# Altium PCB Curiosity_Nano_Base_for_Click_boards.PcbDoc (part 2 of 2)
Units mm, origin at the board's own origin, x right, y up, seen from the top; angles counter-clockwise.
Board outline 74.93 x 107.95 mm, 4 copper layers (Top Layer, Internal Plane 1 Gnd, Internal Plane 2 Pwr, Bottom Layer), stack 1.565 mm thick; 66 components, 59 nets, 464 pads, 89 vias.
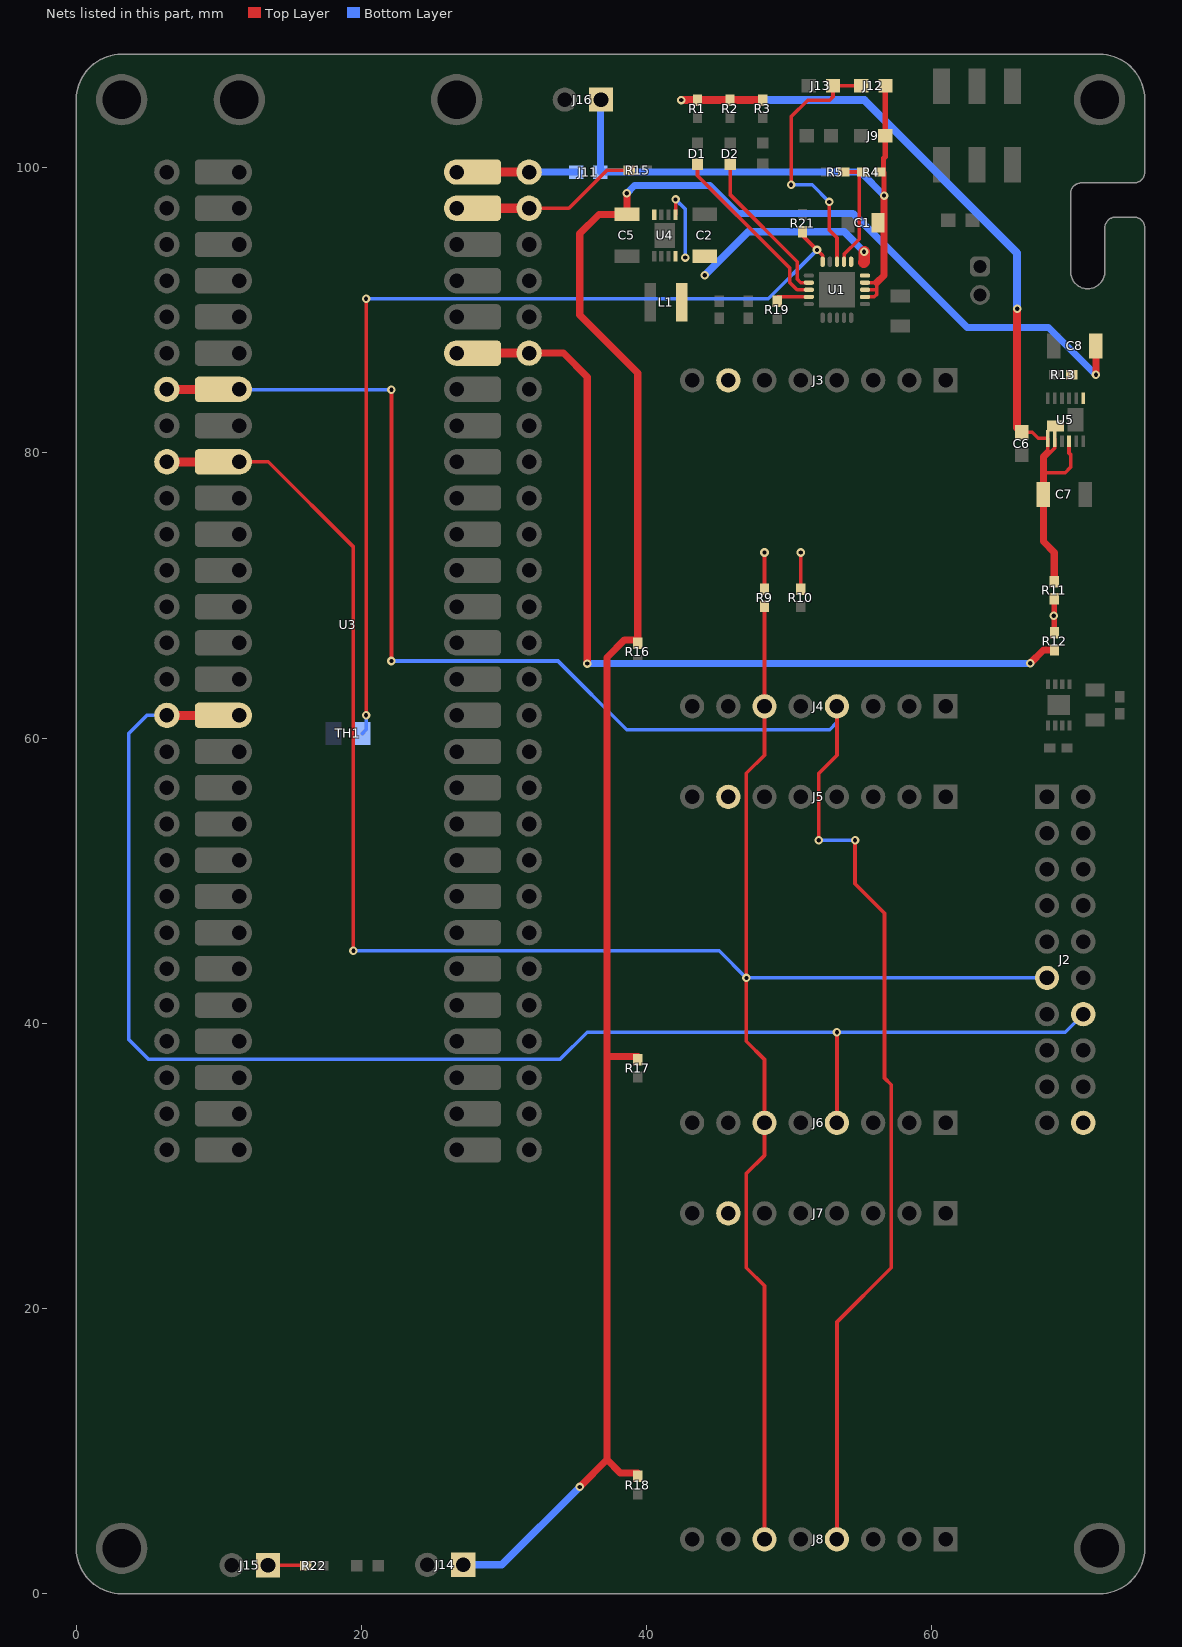
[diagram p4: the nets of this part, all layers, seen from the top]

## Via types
v1: diameter 0.6, hole 0.3, Top Layer to Bottom Layer, tented both sides, 83 vias
v2: diameter 0.6, hole 0.3, Top Layer to Bottom Layer, 6 vias

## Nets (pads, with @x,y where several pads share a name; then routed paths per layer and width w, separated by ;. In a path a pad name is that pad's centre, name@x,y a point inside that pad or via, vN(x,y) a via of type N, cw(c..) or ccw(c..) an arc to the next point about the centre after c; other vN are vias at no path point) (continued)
SDA: J2.11 J4.6 J6.6 J8.6 R9.2 U3.9 | length 155.6
  Top Layer w0.254: U3.9@11.43,79.375 13.462,79.375 19.431,73.406 v1(19.431,45.085) ; R9.2@48.133,69 48.26,68.873 J4.6@48.26,62.23 48.26,58.801 46.99,57.531 v1(46.99,43.18) 46.99,38.735 48.26,37.465 J6.6@48.26,33.02 48.26,30.734 46.99,29.464 46.99,22.86 48.26,21.59 J8.6@48.26,3.81
  Bottom Layer w0.254: v1(19.431,45.085) 42.418,45.085 45.085,45.085 v1(46.99,43.18) J2.11@68.072,43.18
SEL: J12.1 J13.2 U1.3 | length 18.6
  Top Layer w0.254: v2(50.125,98.8) 50.125,103.575 51.29,104.74 52.826,104.74 53.062,104.976 J13.2@53.062,105.75 J12.1@55.05,105.75 ; v2(52.8,97.6) 52.8,95.625 53.34,95.085 U1.3@53.34,93.405
  Bottom Layer w0.254: v2(50.125,98.8) 51.6,98.8 v2(52.8,97.6)
STAT1: D1.1 U1.8 | length 12.5
  Top Layer w0.254: D1.1@43.561,100.23 43.561,99.441 50.038,92.964 50.038,91.948 50.546,91.44 U1.8@51.375,91.44
STAT2: D2.1 U1.7 | length 10.9
  Top Layer w0.254: D2.1@45.847,100.23 45.847,98.122 50.559,93.41 50.559,92.189 50.808,91.94 U1.7@51.375,91.94
T\E\: R19.1 U1.9 | length 2.2
  Top Layer w0.254: R19.1@49.149,90.893 49.196,90.94 U1.9@51.375,90.94
THERM: R21.1 TH1.1 U1.5 | length 66.3
  Top Layer w0.254: v1(20.32,61.595) v1(20.32,90.805) ; R21.1@50.927,95.504 50.927,95.25 v1(51.943,94.234) 52.34,93.837 U1.5@52.34,93.405
  Bottom Layer w0.254: TH1.1@20.066,60.325 20.32,60.579 v1(20.32,61.595) ; v1(20.32,90.805) 48.514,90.805 v1(51.943,94.234)
TX1: J4.4 J8.4 U3.7 | length 128.4
  Top Layer w0.254: v1(22.098,65.405) v1(22.098,84.43) ; v1(52.07,52.832) 52.07,57.523 53.34,58.793 J4.4@53.34,62.23 ; J8.4@53.34,3.81 53.34,19.05 57.15,22.86 57.15,35.687 56.675,36.162 56.675,47.719 54.61,49.784 v1(54.61,52.832)
  Bottom Layer w0.254: U3.7@11.43,84.455 11.455,84.43 v1(22.098,84.43) ; v1(22.098,65.405) 33.782,65.405 38.608,60.579 52.832,60.579 53.34,61.087 J4.4@53.34,62.23 ; v1(52.07,52.832) v1(54.61,52.832)
TX2: J2.14 J6.4 U3.16 | length 99.8
  Top Layer w0.254: J6.4@53.34,33.02 v1(53.34,39.38)
  Bottom Layer w0.254: U3.16@6.35,61.595 4.953,61.595 3.683,60.325 3.683,38.862 5.08,37.465 33.909,37.465 35.824,39.38 v1(53.34,39.38) 69.352,39.38 J2.14@70.612,40.64
VBUS: J11.1 U3.56 | length 3.3
  Bottom Layer w0.5: U3.56@31.75,99.695 J11.1@35.05,99.695
VBUS_VIN: C1.1 J9.2 J11.2 J12.2 J16.1 R4.1 U1.17 U1.18 U1.19 | length 43.2
  Top Layer w0.254: U1.17@55.305,90.94 55.965,90.94 56.132,91.107 56.132,91.44 ; U1.18@55.305,91.44 56.132,91.44 ; U1.19@55.305,91.94 56.132,91.94 56.132,91.44
  Top Layer w0.381: v1(56.642,98.044) 56.642,99.656 56.603,99.695 56.603,100.653 56.73,100.78 J9.2@56.73,102.235 56.73,105.73 J12.2@56.75,105.75
  Top Layer w0.5: 56.132,91.94 56.642,92.45 v1(56.642,98.044)
  Bottom Layer w0.5: J16.1@36.795,104.775 36.75,104.73 J11.2@36.75,99.695 55.005,99.695 v1@56.65,98.05
VCC: R12.1 U3.51 | length 58
  Top Layer w0.5: U3.51@31.75,86.995 34.163,86.995 35.825,85.333 v1(35.825,65.225) ; v1(66.9,65.25) 67.825,66.175 R12.1@68.6,66.175
  Bottom Layer w0.5: v1(35.825,65.225) 66.875,65.225 v1(66.9,65.25)
VCC_P4V4_P5V25: C2.1 L1.1 U1.1 U1.20 U4.1 U4.8 | length 19.4
  Top Layer w0.254: U4.1@42.025,96.7 v1(42.025,97.775)
  Top Layer w0.813: C2.1@44.069,93.726 44.118,93.726 C2.1@44.069,93.775 ; 55.22,93.37 55.245,93.396 v1(55.245,94.107)
  Bottom Layer w0.254: v1(42.025,97.775) 42.7,97.1 v1(42.7,93.7) v1@42.672,93.728
  Bottom Layer w0.5: v1(44.069,92.456) 47.117,95.504 53.848,95.504 v1(55.245,94.107)
VOFF: R15.1 U3.55 | length 7.9
  Top Layer w0.254: U3.55@31.75,97.155 34.544,97.155 37.211,99.822 R15.1@38.52,99.822
VPCC: R4.2 R5.2 U1.2 | length 8.1
  Top Layer w0.254: R5.2@53.813,99.695 R4.2@54.903,99.695 ; U1.2@53.84,93.405 53.84,93.927 54.903,94.99 R4.2@54.903,99.695 ; R4.2@55.153,99.695 R4.2@54.903,99.695
VREG_P3V3: C6.1 C7.1 R1.1 R2.1 R3.1 R11.2 U5.7 U5.8 U5.10 | length 63.9
  Top Layer w0.254: C6.1@66.294,81.445 67.043,81.445 67.467,81.021 67.843,81.026 U5.7@68.117,81.024 ; 67.818,78.613 69.342,78.613 69.723,78.994 69.723,79.883 69.612,79.994 U5.10@69.612,80.82 ; U5.7@68.117,81.021 68.117,80.028 68.305,80.028 68.617,80.34 U5.8@68.617,81.021
  Top Layer w0.5: 68.117,80.028 67.818,79.728 67.818,78.613 C7.1@67.818,77.089 67.818,73.787 68.58,73.025 R11.2@68.58,71.208
  Top Layer w0.559: v1(42.418,104.74) R1.1@43.561,104.74 R2.1@45.847,104.74 R3.1@48.133,104.74 ; v2(65.975,90.1) 65.975,81.764 C6.1@66.294,81.445
  Bottom Layer w0.559: v1(42.418,104.74) 55.26,104.74 65.975,94.025 v2(65.975,90.1) v2@65.975,90.075
VTG_P3V3: J2.20 J3.7 J5.7 J7.7 J15.1 R9.1 R10.1 R11.1 R12.2 R22.1 | length 10.2
  Top Layer w0.254: J15.1@13.44,2 R22.1@16.05,2 ; R9.1@48.26,70.45 v1(48.26,73.013) ; R10.1@50.8,70.45 v1(50.8,73.013)
  Top Layer w0.4: R11.1@68.592,69.77 R11.1@68.58,69.758 68.58,67.395 R12.2@68.6,67.375
  Top Layer w0.5: R22.1@16.05,2 R22.1@16.1,1.95
  other v2: 68.551,68.575
VTG_P5V0: C5.1 C8.1 J14.1 R13.1 R16.1 R17.1 R18.1 U4.4 U5.1 | length 152.9
  Top Layer w0.5: v2(35.3,7.487) 37.211,9.398 ; C5.1@38.581,96.698 C5.1@38.608,96.725 ; v1(38.608,98.208) C5.1@38.608,96.725 ; R18.1@39.37,8.47 38.139,8.47 37.211,9.398 ; R17.1@39.37,37.68 37.265,37.68 37.211,37.626 ; R16.1@39.37,66.89 38.442,66.89 37.211,65.659 37.211,37.626 ; R16.1@39.37,66.929 39.37,85.598 35.306,89.662 35.306,95.377 36.654,96.725 C5.1@38.608,96.725 ; 37.211,9.398 37.211,37.626
  Top Layer w0.508: v1(71.501,85.471) C8.1@71.501,87.503
  Bottom Layer w0.5: J14.1@27.14,2.025 29.838,2.025 v2(35.3,7.487) ; v1(38.608,98.208) 39.15,98.75 44.425,98.75 46.375,96.8 54.475,96.8 62.475,88.8 68.172,88.8 v1(71.501,85.471)
pads on no net: J2.0 J3.0 J4.0 J5.0 J6.0 J7.0 J8.0 SW1.1 SW1.4 U2.1 U2.2 U2.3 U2.6 U2.7 U3.1 U3.3 U3.4 U3.5 U3.6 U3.20 U3.21 U3.22 U3.23 U3.25 U3.26 U3.27 U3.28 U3.29 U3.30 U3.31 U3.32 U3.34 U3.35 U3.36 U3.37 U3.53 U3.54 U4.0 U4.2 U4.3

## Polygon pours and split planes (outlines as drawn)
GND on Top Layer "Top Layer-GND" (solid, remove dead copper, pour order 12): 3.175,0 cw(c3.175,3.175) 0,3.175 0,104.775 cw(c3.175,104.775) 3.175,107.95 71.755,107.95 cw(c71.755,104.775) 74.93,104.775 74.93,99.695 cw(c74.168,99.695) 74.168,98.933 70.485,98.933 ccw(c70.485,98.171) 69.723,98.171 69.723,92.71 ccw(c70.923,92.71) 72.123,92.71 72.123,95.771 cw(c72.885,95.771) 72.885,96.533 74.168,96.533 cw(c74.168,95.771) 74.93,95.771 74.93,3.175 cw(c71.755,3.175) 71.755,0
BAT_SW on Top Layer "BAT_SW_L01_P003" (solid, pour order 3): 53.6,88.7 55.9,88.7 57.4,90.2 58.5,90.2 58.5,91.567 57,91.567 57,91.425 56.175,90.6 54.903,90.6 54.903,89.903 53.6,89.9
GND on Bottom Layer "Bottom Layer-GND" (solid, remove dead copper, pour order 10): 3.175,0 cw(c3.175,3.175) 0,3.175 0,104.775 cw(c3.175,104.775) 3.175,107.95 71.755,107.95 cw(c71.755,104.775) 74.93,104.775 74.93,99.695 cw(c74.168,99.695) 74.168,98.933 70.485,98.933 ccw(c70.485,98.171) 69.723,98.171 69.723,92.71 ccw(c70.923,92.71) 72.123,92.71 72.123,95.771 cw(c72.885,95.771) 72.885,96.533 74.168,96.533 cw(c74.168,95.771) 74.93,95.771 74.93,3.175 cw(c71.755,3.175) 71.755,0
GND on Internal Plane 1 Gnd (split plane): 180 vertices, not listed, extent 0.407,0.407 74.523,107.543
VTG_P3V3 on Internal Plane 2 Pwr (split plane): 180 vertices, not listed, extent 0.407,0.407 74.523,107.543

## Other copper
Top Layer:
  rectangle net VBUS: 29.054,99.2 31.975,100.216
  region net VTG_P5V0: 40.589,97.053 38.1,97.053 38.1,96.342 40.589,96.342
  pour cut-out: 50.662,106.425 50.662,105.075 53.762,105.075 53.762,106.425
  pour cut-out: 54.33,102.91 54.33,101.56 57.43,101.56 57.43,101.658 57.43,102.91
  region net VTG_P5V0: 69.571,85.979 69.571,84.963 70.268,84.963 70.485,84.746 70.485,83.545 72.517,83.545 72.517,85.979
  region net GND: 70.612,83.139 72.517,83.139 72.517,76.2 70.358,76.2 70.358,78.232 71.247,79.121 71.247,79.908 70.714,80.442 70.612,80.442
  region: 70.612,83.139 72.263,83.139
  region: 53.086,94.107
  region net GND: 39.37,93.726 39.37,94.615 41.897,94.615 41.91,94.628 41.91,95.885 37.846,95.885 37.846,93.726
  region net GND: 41.783,94.615 44.831,94.615 44.831,96.774 43.307,96.774 43.307,95.885 41.783,95.885
  region: 4.826,94.361
  region net VCC_P4V4_P5V25: 54.991,92.44 54.991,92.71 54.61,93.091 54.34,93.091 54.34,93.714 54.352,93.726 55.626,93.726 55.626,92.44
  region: 55.88,93.05
  region net VCC_P4V4_P5V25: 41.897,94.023 41.91,94.01 41.91,93.218 42.05,93.078 42.05,90.424 42.672,90.424 44.958,92.71 44.958,94.107 42.037,94.107
  region net NetL1_2: 40.208,94.17 40.208,92.913 39.65,92.355 39.65,89.205 40.65,89.205 40.65,91.958 40.665,91.973 40.665,94.17
Bottom Layer:
  region: 70.612,83.82

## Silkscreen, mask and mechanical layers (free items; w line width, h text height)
Top Overlay:
  circle w0.254: c3.175,3.175 r2.54
  circle w0.254: c71.755,3.175 r2.54
  circle w0.254: c71.755,104.775 r2.54
  circle w0.254: c3.175,104.775 r2.54
  region: 52.705,104.013
  region: 65.493,97.775 66.525,98.156 66.525,97.394
  lines w0.15: 49.2,100.285 49.2,107.525 ; 49.25,100.285 58.325,100.285
  lines w0.254: 11.43,107.315 15.164,107.315 ; 22.86,107.366 15.24,107.366 15.24,101.6 22.86,101.6 22.86,107.264 22.911,107.315 26.619,107.315 ; 66.294,97.775 67.652,97.775
  text "PS" at 47.592,107.569 h1.75 r270
  text "S2" at 45.306,107.506 h1.75 r270
  text "S1" at 43.02,107.295 h1.75 r270
  text "0.5A" at 50.612,106.6 h1.52
  text "1.6A" at 54.5,106.6 h1.52
  text "GND" at 32.237,106.575 h1.52
  text "VBUS" at 35.525,106.575 h1.52
  text "VBUS-Limit" at 49.4,103.45 h1.8
  text "VOFF" at 37.631,100.8 h1.52
  text "GND" at 1.517,100.711 h1.75
  text "GND" at 70.097,100.711 h1.75
  text "0.1A" at 50.612,100.44 h1.52
  text "0.5A" at 54.5,100.44 h1.52
  text "NC" at 2.903,99.154 h1.75
  text "VBUS" at 33.147,99.154 h1.75
  text "Battery On" at 58.5,97.5 h1.52
  text "ID" at 3.579,96.614 h1.75
  text "VOFF" at 33.147,96.614 h1.75
  text "Li-Ion/LiPo" at 66.929,95.259 h1.52 r270
  text "Battery" at 65.659,94.234 h1.52 r270
  text "NC" at 2.903,94.074 h1.75
  text "NC" at 33.147,94.074 h1.75
  text "+" at 59.02,93.575 h1.5 r270
  text "-" at 59.02,91.575 h1.5 r270
  text "NC" at 2.903,91.534 h1.75
  text "NC" at 33.147,91.534 h1.75
  text "NC" at 2.903,88.994 h1.75
  text "GND" at 33.147,88.994 h1.75
  text "NC" at 2.903,86.454 h1.75
  text "VCC" at 33.147,86.454 h1.75
  text "TX1" at 2.497,83.914 h1.75
  text "RST1" at 33.147,83.914 h1.75
  text "RX1" at 2.458,81.374 h1.75
  text "INT1" at 33.147,81.374 h1.75
  text "SDA" at 1.878,78.834 h1.75
  text "PWM3" at 33.147,78.834 h1.75
  text "SCL" at 2.035,76.294 h1.75
  text "PWM2" at 33.147,76.294 h1.75
  text "MOSI" at 1.268,73.754 h1.75
  text "PWM1" at 33.147,73.754 h1.75
  text "3V3" at 69.675,71.425 h1.52 r270
  text "MISO" at 1.21,71.214 h1.75
  text "AN3" at 33.147,71.214 h1.75
  text "SCK" at 1.881,68.674 h1.75
  text "AN2" at 33.147,68.674 h1.75
  text "VCC" at 69.725,68.25 h1.52 r270
  text "CS1" at 2.289,66.134 h1.75
  text "AN1" at 33.147,66.134 h1.75
  text "GND" at 1.655,63.594 h1.75
  text "GND" at 33.147,63.594 h1.75
  text "TX2" at 2.286,61.054 h1.75
  text "CS3" at 33.147,61.054 h1.75
  text "RX2" at 2.247,58.514 h1.75
  text "CS2" at 33.147,58.514 h1.75
  text "EXT1" at 71.592,57.76 h1.5
  text "1" at 67.845,57.518 h1.5
  text "2" at 70.288,57.51 h1.5
  text "INT2" at 1.69,55.974 h1.75
  text "RST3" at 33.147,55.974 h1.75
  text "RST2" at 1.206,53.434 h1.75
  text "INT3" at 33.147,53.434 h1.75
  text "NC" at 2.903,50.894 h1.75
  text "NC" at 33.147,50.894 h1.75
  text "NC" at 2.903,48.354 h1.75
  text "NC" at 33.147,48.354 h1.75
  text "NC" at 2.903,45.814 h1.75
  text "NC" at 33.147,45.814 h1.75
  text "NC" at 2.903,43.274 h1.75
  text "NC" at 33.147,43.274 h1.75
  text "GND" at 1.655,40.734 h1.75
  text "GND" at 33.147,40.734 h1.75
  text "NC" at 2.903,38.194 h1.75
  text "NC" at 33.147,38.194 h1.75
  text "NC" at 2.903,35.654 h1.75
  text "NC" at 33.147,35.654 h1.75
  text "NC" at 2.903,33.114 h1.75
  text "NC" at 33.147,33.114 h1.75
  text "19" at 67.377,30.686 h1.5
  text "20" at 69.909,30.685 h1.5
  text "NC" at 2.903,30.574 h1.75
  text "NC" at 33.147,30.574 h1.75
  text "Xplained Pro Extension" at 72.5,30.25 h2.18 r270
  text "M" at 7.71,9.903 h12
  text "Curiosity Nano Adapter" at 7.836,6.604 h2.29
  text "GND" at 1.524,6.096 h1.75
  text "GND" at 70.104,6.096 h1.75
  text "GND" at 9.35,3.9 h1.52
  text "3V3" at 12.65,3.9 h1.52
  text "GND" at 22.9,3.875 h1.52
  text "5V0" at 26.225,3.875 h1.52
  text "POWER" at 16.3,3.075 h1.75
Bottom Overlay:
  lines w0.2: 66.748,9.215 ccw(c70.612,10.25) 74.237,8.56
  lines w0.305: 37.973,66.929 37.973,15.24 0.762,15.24 0.762,70.485 37.973,70.485 37.973,68.961
  text "GND" at 35.125,106.575 h1.52
  text "VBUS" at 39.158,106.575 h1.52
  text "GND" at 13.081,101.427 h1.75
  text "GND" at 28.321,101.427 h1.75
  text "GND" at 4.833,101.25 h1.75
  text "GND" at 73.413,101.25 h1.75
  text "VBUS" at 37.986,100.65 h1.75
  text "NC" at 4.97,99.154 h1.75
  text "VOFF" at 37.118,96.647 h1.75
  text "ID" at 4.97,96.614 h1.75
  text "NC" at 35.214,94.107 h1.75
  text "NC" at 4.97,94.074 h1.75
  text "+" at 65.725,93.575 h1.5 r90
  text "-" at 65.725,91.575 h1.5 r90
  text "NC" at 35.214,91.567 h1.75
  text "NC" at 4.97,91.534 h1.75
  text "W" at 16.635,91.45 h8.25
  text "Battery" at 59.602,89.765 h1.52 r270
  text "GND" at 36.462,89.027 h1.75
  text "NC" at 4.97,88.994 h1.75
  text "Li-Ion/LiPo" at 60.872,88.919 h1.52 r270
  text "VCC" at 36.301,86.487 h1.75
  text "NC" at 4.97,86.454 h1.75
  text "RST1" at 36.7,83.947 h1.75
  text "TX1" at 4.969,83.914 h1.75
  text "c" at 22.541,83.578 h6.8
  text "INT1" at 36.216,81.407 h1.75
  text "RX1" at 4.97,81.374 h1.75
  text "PWM3" at 37.546,78.867 h1.75
  text "SDA" at 4.969,78.834 h1.75
  text "PWM2" at 37.556,76.327 h1.75
  text "SCL" at 4.969,76.294 h1.75
  text "PWM1" at 37.344,73.787 h1.75
  text "MOSI" at 4.97,73.754 h1.75
  text "AN3" at 36.172,71.272 h1.75
  text "MISO" at 4.97,71.214 h1.75
  text "AN2" at 36.182,68.732 h1.75
  text "SCK" at 4.969,68.674 h1.75
  text "AN1" at 35.971,66.325 h1.75
  text "CS1" at 4.97,66.134 h1.75
  text "GND" at 36.462,63.627 h1.75
  text "GND" at 4.97,63.594 h1.75
  text "TX2" at 4.969,61.054 h1.75
  text "CS3" at 36.029,61.012 h1.75
  text "RX2" at 4.97,58.514 h1.75
  text "CS2" at 36.04,58.472 h1.75
  text "1" at 68.299,57.518 h1.5
  text "2" at 70.936,57.51 h1.5
  text "RST3" at 36.901,56.007 h1.75
  text "INT2" at 4.97,55.974 h1.75
  text "XPLAINED PRO" at 22.825,54.55 h0.67
  text "EXTENSION HEADER" at 23.95,53.5 h0.67
  text "INT3" at 36.417,53.467 h1.75
  text "RST2" at 4.97,53.434 h1.75
  text "ID" at 18.8,51.175 h1.3
  text "GND" at 23.075,51.175 h1.3
  text "NC" at 35.214,50.927 h1.75
  text "NC" at 4.97,50.894 h1.75
  text "AN2" at 18.8,49.05 h1.3
  text "AN3" at 23.075,49.05 h1.3
  text "NC" at 35.214,48.387 h1.75
  text "NC" at 4.97,48.354 h1.75
  text "RST2" at 18.8,46.925 h1.3
  text "RST3" at 23.075,46.925 h1.3
  text "NC" at 35.214,45.847 h1.75
  text "NC" at 4.97,45.814 h1.75
  text "PWM2" at 18.8,44.8 h1.3
  text "PWM3" at 23.075,44.8 h1.3
  text "NC" at 35.214,43.307 h1.75
  text "NC" at 4.97,43.274 h1.75
  text "INT2" at 18.8,42.675 h1.3
  text "CS3" at 23.075,42.675 h1.3
  text "GND" at 36.462,40.767 h1.75
  text "GND" at 4.97,40.734 h1.75
  text "XPLAINED PRO" at 73.55,40.587 h0.67 r270
  text "SDA" at 18.8,40.55 h1.3
  text "SCL" at 23.075,40.55 h1.3
  text "EXTENSION HEADER" at 72.5,39.244 h0.67 r270
  text "RX2" at 18.8,38.425 h1.3
  text "TX2" at 23.075,38.425 h1.3
  text "NC" at 35.214,38.227 h1.75
  text "NC" at 4.97,38.194 h1.75
  text "CS2" at 18.8,36.3 h1.3
  text "MOSI" at 23.075,36.3 h1.3
  text "NC" at 35.214,35.687 h1.75
  text "NC" at 4.97,35.654 h1.75
  text "MISO" at 18.8,34.175 h1.3
  text "SCK" at 23.075,34.175 h1.3
  text "NC" at 35.214,33.147 h1.75
  text "NC" at 4.97,33.114 h1.75
  text "GND" at 18.8,32.05 h1.3
  text "3V3" at 23.075,32.05 h1.3
  text "19" at 68.767,30.686 h1.5
  text "20" at 71.315,30.685 h1.5
  text "NC" at 4.97,30.574 h1.75
  text "NC" at 35.214,30.574 h1.75
  text "ATTACH OPTIONAL" at 29.591,26.035 h2.54
  text "BATTERY PACK IN" at 28.829,22.86 h2.54
  text "THIS AREA." at 24.511,19.685 h2.54
  text "'.PCBNumber_TLM' Rev'.ProjectRevisionFAB'" at 26.249,8.891 h2
  text "Microchip © 2018" at 28.408,5.462 h2
  text "GND" at 12.238,3.9 h1.52
  text "3V3" at 14.997,3.9 h1.52
  text "GND" at 25.788,3.875 h1.52
  text "5V0" at 28.561,3.875 h1.52
  text "GND" at 8.9,2.634 h1.75
  text "GND" at 69.325,2.634 h1.75
Board (M1):
  the board outline again, w0.254
Dimension (M6):
  circle w0.254: c3.175,3.175 r1.35
  circle w0.254: c71.755,3.175 r1.35
  circle w0.254: c71.755,104.775 r1.35
  circle w0.254: c3.175,104.775 r1.35
  circle w0.254: c26.67,104.775 r1.35
  circle w0.254: c11.43,104.775 r1.35
Conn Doc (M7):
  drawing of 196 lines, arcs and shapes, not listed
  text "Curiosity Nano / footprint" at 12.215,102.1 h1
  text "U3" at 18.217,100.071 h1
  text "NC" at 12.7,99.187 h1.75
  text "VBUS" at 21.1,99.154 h1.75
  text "ID" at 12.7,96.647 h1.75
  text "VOFF" at 21.3,96.647 h1.75
  text "J1" at 62.157,95.7 h1
  text "Li-Ion/LiPo" at 59.309,95.259 h1.52 r270
  text "Battery" at 58.039,94.234 h1.52 r270
  text "NC" at 12.7,94.107 h1.75
  text "NC" at 23.204,94.107 h1.75
  text "+" at 60.925,93.375 h0.9 r270
  text "NC" at 12.7,91.567 h1.75
  text "NC" at 23.204,91.567 h1.75
  text "-" at 60.925,91.375 h0.9 r270
  text "NC" at 12.7,89.027 h1.75
  text "GND" at 21.956,89.027 h1.75
  text "NC" at 12.7,86.487 h1.75
  text "VCC" at 22.118,86.487 h1.75
  text "J3" at 63.271,85.923 h1 r270
  text "TX1" at 12.701,83.947 h1.75
  text "RST1" at 21.718,83.947 h1.75
  text "GND" at 42.611,82.55 h1.78 r270
  text "+3.3V" at 45.158,82.55 h1.78 r270
  text "MOSI" at 47.691,82.55 h1.78 r270
  text "MISO" at 50.231,82.55 h1.78 r270
  text "SCK" at 52.771,82.55 h1.78 r270
  text "CS1" at 55.311,82.55 h1.78 r270
  text "RST1" at 57.851,82.55 h1.78 r270
  text "AN1" at 60.391,82.55 h1.78 r270
  text "RX1" at 12.7,81.407 h1.75
  text "INT1" at 22.202,81.407 h1.75
  text "mikroBUS Socket" at 35.658,80.741 h1 r270
  text "E" at 62.396,79.512 h5.75 r270
  text "SDA" at 12.701,78.867 h1.75
  text "PWM3" at 20.873,78.867 h1.75
  text "SCL" at 12.701,76.327 h1.75
  text "PWM2" at 20.862,76.327 h1.75
  text "1" at 41.783,74.822 h7.62 r270
  text "MOSI" at 12.7,73.787 h1.75
  text "PWM1" at 21.074,73.787 h1.75
  text "MISO" at 12.7,71.247 h1.75
  text "AN3" at 22.246,71.247 h1.75
  text "PWM1" at 60.391,69.113 h1.78 r270
  text "SCK" at 12.701,68.707 h1.75
  text "AN2" at 22.236,68.707 h1.75
  text "GND" at 42.611,68.123 h1.78 r270
  text "SDA" at 47.691,67.954 h1.78 r270
  text "INT1" at 57.851,67.763 h1.78 r270
  text "SCL" at 50.231,67.722 h1.78 r270
  text "+5V" at 45.161,67.53 h1.78 r270
  text "RX1" at 55.311,67.434 h1.78 r270
  text "TX1" at 52.771,67.344 h1.78 r270
  text "AN1" at 22.447,66.294 h1.75
  text "CS1" at 12.701,66.167 h1.75
  text "GND" at 12.7,63.627 h1.75
  text "GND" at 21.956,63.627 h1.75
  text "J4" at 63.271,63.063 h1 r270
  text "TX2" at 12.701,61.087 h1.75
  text "CS3" at 22.389,61.087 h1.75
  text "RX2" at 12.7,58.547 h1.75
  text "CS2" at 22.379,58.547 h1.75
  text "J3" at 68.509,57.2 h1
  text "J5" at 63.271,56.713 h1 r270
  text "INT2" at 12.7,56.007 h1.75
  text "RST3" at 21.517,56.007 h1.75
  text "Xplained Pro Extension" at 72.8,54.947 h1 r270
  text "RST2" at 12.7,53.467 h1.75
  text "INT3" at 22.001,53.467 h1.75
  text "GND" at 42.611,53.34 h1.78 r270
  text "+3.3V" at 45.158,53.34 h1.78 r270
  text "MOSI" at 47.691,53.34 h1.78 r270
  text "MISO" at 50.231,53.34 h1.78 r270
  text "SCK" at 52.771,53.34 h1.78 r270
  text "CS2" at 55.311,53.34 h1.78 r270
  text "RST2" at 57.851,53.34 h1.78 r270
  text "AN2" at 60.391,53.34 h1.78 r270
  text "mikroBUS Socket" at 35.658,51.531 h1 r270
  text "NC" at 12.7,50.927 h1.75
  text "NC" at 23.204,50.927 h1.75
  text "E" at 62.396,50.302 h5.75 r270
  text "NC" at 12.7,48.387 h1.75
  text "NC" at 23.204,48.387 h1.75
  text "2" at 41.783,46.101 h7.62 r270
  text "NC" at 12.7,45.847 h1.75
  text "NC" at 23.204,45.847 h1.75
  text "NC" at 12.7,43.307 h1.75
  text "NC" at 23.204,43.307 h1.75
  text "GND" at 12.7,40.767 h1.75
  text "GND" at 21.956,40.767 h1.75
  text "PWM2" at 60.391,40.111 h1.78 r270
  text "GND" at 42.611,38.913 h1.78 r270
  text "SDA" at 47.691,38.744 h1.78 r270
  text "INT2" at 57.851,38.76 h1.78 r270
  text "SCL" at 50.231,38.512 h1.78 r270
  text "RX2" at 55.311,38.432 h1.78 r270
  text "TX2" at 52.771,38.341 h1.78 r270
  text "+5V" at 45.161,38.32 h1.78 r270
  text "NC" at 12.7,38.227 h1.75
  text "NC" at 23.204,38.227 h1.75
  text "NC" at 12.7,35.687 h1.75
  text "NC" at 23.204,35.687 h1.75
  text "J6" at 63.271,33.853 h1 r270
  text "NC" at 12.7,33.147 h1.75
  text "NC" at 23.204,33.147 h1.75
  text "NC" at 12.7,30.607 h1.75
  text "NC" at 23.204,30.607 h1.75
  text "J7" at 63.271,27.503 h1 r270
  text "GND" at 42.611,24.13 h1.78 r270
  text "+3.3V" at 45.158,24.13 h1.78 r270
  text "MOSI" at 47.691,24.13 h1.78 r270
  text "MISO" at 50.231,24.13 h1.78 r270
  text "SCK" at 52.771,24.13 h1.78 r270
  text "CS3" at 55.311,24.13 h1.78 r270
  text "RST3" at 57.851,24.13 h1.78 r270
  text "AN3" at 60.391,24.13 h1.78 r270
  text "mikroBUS Socket" at 35.658,22.321 h1 r270
  text "E" at 62.396,21.092 h5.75 r270
  text "3" at 41.783,16.888 h7.62 r270
  text "PWM3" at 60.391,10.921 h1.78 r270
  text "GND" at 42.611,9.703 h1.78 r270
  text "INT3" at 57.851,9.57 h1.78 r270
  text "SDA" at 47.691,9.543 h1.78 r270
  text "SCL" at 50.231,9.31 h1.78 r270
  text "+5V" at 45.161,9.119 h1.78 r270
  text "RX1" at 55.311,9.022 h1.78 r270
  text "TX1" at 52.771,8.932 h1.78 r270
  text "J8" at 63.271,4.643 h1 r270
TITLE (M16):
  lines w0.1: 241.795,-67.305 323.615,-67.305 ; 298.795,-59.805 298.795,-62.805 323.615,-62.805 ; 312.335,-84.44 312.335,-83.17 ; 312.335,-83.805 322.495,-83.805 ; 312.495,-82.605 312.495,-81.605 ; 312.495,-82.105 322.495,-82.105 ; 314.875,-84.44 314.875,-83.17 ; 317.415,-84.44 317.415,-83.17 ; 317.495,-82.405 317.495,-81.805 ; 319.955,-84.44 319.955,-83.17 ; 322.495,-84.44 322.495,-83.17 ; 322.495,-82.605 322.495,-81.605 ; 323.615,-62.805 323.615,-62.805
  lines w0.127: -52.305,-29.98 -47.225,-29.98 ; -52.305,30.345 -47.225,30.345 ; -52.305,90.67 -47.225,90.67 ; 11.195,-90.305 11.195,-85.225 ; 11.195,145.915 11.195,150.995 ; 74.695,-90.305 74.695,-85.225 ; 74.695,145.915 74.695,150.995 ; 138.195,-90.305 138.195,-85.225 ; 138.195,145.915 138.195,150.995 ; 173.755,-85.225 209.315,-85.225 ; 201.695,-90.305 201.695,-85.225 ; 201.695,145.915 201.695,150.995 ; 207.795,-85.225 207.795,-59.805 323.615,-59.805 ; 241.795,-85.225 241.795,-59.805 ; 241.795,-80.805 323.615,-80.805 ; 241.795,-74.805 323.615,-74.805 ; 241.795,-68.805 323.615,-68.805 ; 265.195,-90.305 265.195,-85.225 ; 265.195,145.915 265.195,150.995 ; 269.795,-85.225 269.795,-68.805 ; 287.795,-80.805 287.795,-74.805 ; 300.795,-85.225 300.795,-80.805 ; 308.295,-85.225 308.295,-74.805 ; 323.615,-54.745 323.615,-85.225 ; 323.615,-29.98 328.695,-29.98 ; 323.615,30.345 328.695,30.345 ; 323.615,90.67 328.695,90.67 ; 323.615,-85.225 -47.225,-85.225 -47.225,145.915 323.615,145.915 323.615,-85.225 ; -52.305,-90.305 328.695,-90.305 328.695,150.995 -52.305,150.995 -52.305,-90.305
  lines w0.254: 201.795,145.695 201.795,141.195 ; 212.795,136.695 212.795,141.195 212.795,145.695 ; 225.295,136.695 225.295,141.195 225.295,145.695 ; 303.795,136.695 303.795,141.195 303.795,145.695 ; 323.295,136.695 201.795,136.695 201.795,141.195 ; 323.295,141.195 201.795,141.195
  text "1" at -21.029,147.693 h1.78
  text "2" at 42.361,147.693 h1.78
  text "3" at 105.59,147.693 h1.78
  text "4" at 169.259,147.693 h1.78
  text "5" at 232.734,147.693 h1.78
  text "6" at 296.361,147.693 h1.78
  text "REV" at 204.295,142.695 h1.27
  text "ECO" at 214.295,142.695 h1.27
  text "Comments" at 260.795,142.195 h1.27
  text "Date" at 308.795,142.195 h1.27
  text "A" at -50.4,118.661 h1.78
  text "A" at 325.52,118.661 h1.78
  text "B" at -50.4,58.209 h1.78
  text "B" at 325.52,58.209 h1.78
  text "C" at -50.4,-2.116 h1.78
  text "C" at 325.52,-2.116 h1.78
  text "PCBA NO:" at 299.795,-61.805 h1
  text "'.PCBANumber_TLM'" at 307.721,-62.205 h1.91
  text "D" at -50.4,-62.314 h1.78
  text "TITLE:" at 242.795,-62.305 h1.14
  text "D" at 325.52,-62.314 h1.78
  text ".ProjectTitle" at 242.795,-66.305 h2.3
  text "PCB DESIGNER:" at 242.795,-70.805 h1.14
  text "GERBER FILE:" at 270.795,-70.805 h1.14
  text ".ProjectDrawnBy" at 242.795,-73.805 h1.78
  text "M" at 210.795,-75.805 h15.24
  text "ENGINEER:" at 242.795,-76.805 h1.14
  text "BOARD NUMBER:" at 270.795,-76.805 h1.14
  text "DOCUMENT NUMBER:" at 288.545,-76.805 h1.14
  text "DATE:" at 309.495,-76.805 h1.14
  text "Microchip Technology Inc." at 209.565,-79.065 h1.27
  text ".ProjectEngineer" at 242.795,-79.805 h1.78
  text ".PRINT_DATE" at 309.495,-79.805 h1.5
  text "'.PCBNumber_TLM'" at 271.856,-79.832 h1.91
  text "'.PCBANumber_TLM'" at 290.093,-79.908 h1.73
  text "2355 W. Chandler Blvd." at 210.795,-81.805 h1.27
  text "LAYER NAME:" at 270.795,-82.305 h1.14
  text "10mm" at 308.795,-82.405 h0.7
  text "PCB FILE NAME:" at 242.795,-82.555 h1.14
  text "REV:" at 301.545,-82.555 h1.14
  text "400mil" at 308.534,-84.099 h0.7
  text "Chandler, AZ  85224" at 211.795,-84.305 h1.27
  text ".PCB_FILE_NAME_NO_PATH" at 242.795,-84.555 h1.14
  text "1" at -21.029,-88.527 h1.78
  text "2" at 42.361,-88.527 h1.78
  text "3" at 105.59,-88.527 h1.78
  text "4" at 169.259,-88.527 h1.78
  text "5" at 232.734,-88.527 h1.78
  text "6" at 296.361,-88.527 h1.78
Drill Drawing:
  drawing of 411 lines, arcs and shapes, not listed
  text "THIS PCB TO BE MANUFACTURED TO MEET ALL ACCEPTANCE LEVELS" at 190.401,103.872 h1.78
  text "OF A CLASS 2 PCB PER ANSI/IPC-A-600G." at 190.401,100.062 h1.78
  text "MATERIAL:" at 190.401,95.442 h1.78
  text "FR-4 or Equivalent" at 210.721,95.442 h1.78
  text "CONTROLLED IMPEDANCE" at 266.912,91.21 h1.78
  text "MULTILAYER" at 216.436,91.092 h1.78
  text "4" at 239.931,91.092 h1.78
  text "LAYERS" at 244.376,91.092 h1.78
  text "X" at 211.709,90.67 h2.6
  text "Cu WEIGHT EXTERNAL LAYERS" at 210.721,86.242 h1.78
  text "1OZ" at 262.791,86.242 h1.78
  text "FINISHED" at 272.316,86.242 h1.78
  text "Cu WEIGHT INTERNAL LAYERS" at 210.721,81.392 h1.78
  text "1OZ" at 262.791,81.392 h1.78
  text "FINISHED" at 272.316,81.392 h1.78
  text "0.062" at 262.001,76.581 h1.78
  text "in" at 272.161,76.581 h1.78
  text "FINISHED OVERALL THICKNESS" at 210.721,76.542 h1.78
  text "10" at 286.921,76.542 h1.78
  text "%" at 295.176,76.542 h1.78
  text "COPPER THIEVING ALLOWED" at 210.912,71.71 h1.78
  text "YES" at 267.912,71.71 h1.78
  text "NO" at 284.912,71.71 h1.78
  text "X" at 279.503,71.21 h2.6
  text "FINISH:" at 190.412,67.21 h1.78
  text "LEAD-FREE HOT AIR LEVELING" at 216.412,66.91 h1.78
  text "IMMERSION GOLD" at 216.436,61.372 h1.78
  text "X" at 211.709,60.96 h2.6
  text "IMMERSION TIN" at 216.436,55.872 h1.78
  text "SMOBC WITH SELECTIVE GOLD PLATING ON LANDS" at 216.436,52.167 h1.78
  text "INDICATED. 1um GOLD OVER 5-10 um NICKEL" at 216.436,48.357 h1.78
  text "SOLDERMASK" at 210.721,41.522 h1.78
  text "DYNACHEM EPIC 200 LPI OR EQUIVALENT" at 232.311,41.522 h1.78
  text "SOLDERMASK COLOR" at 210.721,35.172 h1.78
  text "RED" at 242.471,35.172 h1.78
  text "SILKSCREEN COLOR" at 210.721,28.822 h1.78
  text "WHITE" at 242.471,28.822 h1.78
  text "ALL HOLES TO BE LOCATED BY THE COORDINATES FROM THE NC DRILL DATA PROVIDED." at 190.373,22.479 h1.78
  text "PCB REV" at 256.997,16.205 h1.78
  text "USE ARTWORK SET NO." at 190.401,16.122 h1.78
  text ".ProjectRevisionART" at 271.526,16.129 h1.78
  text "'.PCBNumber_TLM'" at 226.949,16.104 h1.91
  text "ALL UL LOGO, MANUFACTURER'S ID, AND DATE CODES SHALL BE PLACED" at 190.401,9.772 h1.78
  text "ON THE BOTTOM SIDE UNLESS OTHERWISE INDICATED." at 190.401,5.962 h1.78
  text "ANY ALTERNATIVES TO THE ABOVE SPECIFICATIONS MUST FIRST BE APPROVED." at 189.912,0.71 h1.78
  text "Layer" at 192.544,-13.843 h1.52
  text "Name" at 202.955,-13.843 h1.52
  text "Material" at 235.204,-13.843 h1.52
  text "Thickness" at 257.042,-13.843 h1.52
  text "Constant" at 273.548,-13.843 h1.52
  text "Board Layer Stack" at 288.022,-13.843 h1.52
  text "1" at 192.544,-16.891 h1.52
  text "Top Overlay" at 202.955,-16.891 h1.52
  text "2" at 192.544,-19.939 h1.52
  text "Top Solder" at 202.955,-19.939 h1.52
  text "Solder Resist" at 235.204,-19.939 h1.52
  text "0,40mil" at 257.042,-19.939 h1.52
  text "3,5" at 273.548,-19.939 h1.52
  text "3" at 192.544,-22.987 h1.52
  text "Top Layer" at 202.955,-22.987 h1.52
  text "Copper" at 235.204,-22.987 h1.52
  text "1,40mil" at 257.042,-22.987 h1.52
  text "4" at 192.544,-26.035 h1.52
  text "Dielectric 1" at 202.955,-26.035 h1.52
  text "FR-4" at 235.204,-26.035 h1.52
  text "5,00mil" at 257.042,-26.035 h1.52
  text "4,2" at 273.548,-26.035 h1.52
  text "5" at 192.544,-29.083 h1.52
  text "Internal Plane 1 Gnd" at 202.955,-29.083 h1.52
  text "Copper" at 235.204,-29.083 h1.52
  text "1,40mil" at 257.042,-29.083 h1.52
  text "Symbol" at 99.346,-29.21 h1.52
  text "Hit Count" at 110.189,-29.21 h1.52
  text "Finished Hole Size" at 125.095,-29.21 h1.52
  text "Plated" at 153.712,-29.21 h1.52
  text "Hole Type" at 164.556,-29.21 h1.52
  text "6" at 192.544,-32.131 h1.52
  text "Dielectric 2" at 202.955,-32.131 h1.52
  text "46,00mil" at 257.042,-32.131 h1.52
  text "4,2" at 273.548,-32.131 h1.52
  text "89" at 110.189,-32.385 h1.27
  text "11,81mil (0,300mm)" at 125.095,-32.385 h1.27
  text "PTH" at 153.712,-32.385 h1.27
  text "Round" at 164.556,-32.385 h1.27
  text "7" at 192.544,-35.179 h1.52
  text "Internal Plane 2 Pwr" at 202.955,-35.179 h1.52
  text "Copper" at 235.204,-35.179 h1.52
  text "1,40mil" at 257.042,-35.179 h1.52
  text "2" at 110.189,-35.56 h1.27
  text "35,43mil (0,900mm)" at 125.095,-35.56 h1.27
  text "PTH" at 153.712,-35.56 h1.27
  text "Round" at 164.556,-35.56 h1.27
  text "8" at 192.544,-38.227 h1.52
  text "Dielectric 3" at 202.955,-38.227 h1.52
  text "FR-4" at 235.204,-38.227 h1.52
  text "5,00mil" at 257.042,-38.227 h1.52
  text "4,2" at 273.548,-38.227 h1.52
  text "186" at 110.189,-38.735 h1.27
  text "40,16mil (1,020mm)" at 125.095,-38.735 h1.27
  text "PTH" at 153.712,-38.735 h1.27
  text "Round" at 164.556,-38.735 h1.27
  text "9" at 192.544,-41.275 h1.52
  text "Bottom Layer" at 202.955,-41.275 h1.52
  text "Copper" at 235.204,-41.275 h1.52
  text "1,40mil" at 257.042,-41.275 h1.52
  text "6" at 110.189,-41.91 h1.27
  text "106,30mil (2,700mm)" at 125.095,-41.91 h1.27
  text "PTH" at 153.712,-41.91 h1.27
  text "Round" at 164.556,-41.91 h1.27
  text "10" at 192.544,-44.323 h1.52
  text "Bottom Solder" at 202.955,-44.323 h1.52
  text "Solder Resist" at 235.204,-44.323 h1.52
  text "0,40mil" at 257.042,-44.323 h1.52
  text "3,5" at 273.548,-44.323 h1.52
  text "283 Total" at 110.189,-45.085 h1.27
  text "11" at 192.544,-47.371 h1.52
  text "Bottom Overlay" at 202.955,-47.371 h1.52
  text "'.PCBNumber_TLM'" at 290.093,-79.908 h1.73
  text ".ProjectRevisionFAB" at 305.473,-84.377 h1.5

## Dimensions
71.755,104.775 to 74.93,104.775 on Dimension (M6)
3.175,104.775 to 3.175,107.95 on Dimension (M6)
11.43,104.775 to 26.67,104.775 on Dimension (M6)
0,104.775 to 11.43,104.775 on Dimension (M6)
43.18,85.09 to 71.755,107.95 on Conn Pos (M4)
71.755,0 to 43.18,3.81 on Conn Pos (M4)
43.18,26.67 to 43.18,33.02 on Conn Pos (M4)
43.18,3.81 to 43.18,26.67 on Conn Pos (M4)
43.18,33.02 to 43.18,55.88 on Conn Pos (M4)
70.612,33.02 to 68.072,33.02 on Conn Pos (M4)
70.612,33.02 to 71.755,0 on Conn Pos (M4)
63.373,91.075 to 63.373,93.075 on Conn Pos (M4)
63.373,91.075 to 74.93,95.771 on Conn Pos (M4)
43.18,85.09 to 45.72,85.09 on Conn Pos (M4)
43.18,55.88 to 43.18,62.23 on Conn Pos (M4)
43.18,62.23 to 43.18,85.09 on Conn Pos (M4)
43.18,85.09 to 74.93,104.775 on Conn Pos (M4)
11.43,31.115 to 0,3.175 on Conn Pos (M4)
26.67,31.115 to 11.43,31.115 on Conn Pos (M4)
11.43,31.115 to 11.43,33.655 on Conn Pos (M4)
3.175,0 to 11.43,31.115 on Conn Pos (M4)
26.67,104.775 to 33.1,110.1 on Dimension (M6)
70.923,91.51 to 70.485,98.933 on Dimension (M6)
74.168,98.933 to 74.168,96.533 on Dimension (M6)
71.755,107.95 to 74.168,98.933 on Dimension (M6)
0,3.175 to 74.93,3.175 on Dimension (M6)
3.175,0 to 3.175,107.95 on Dimension (M6)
